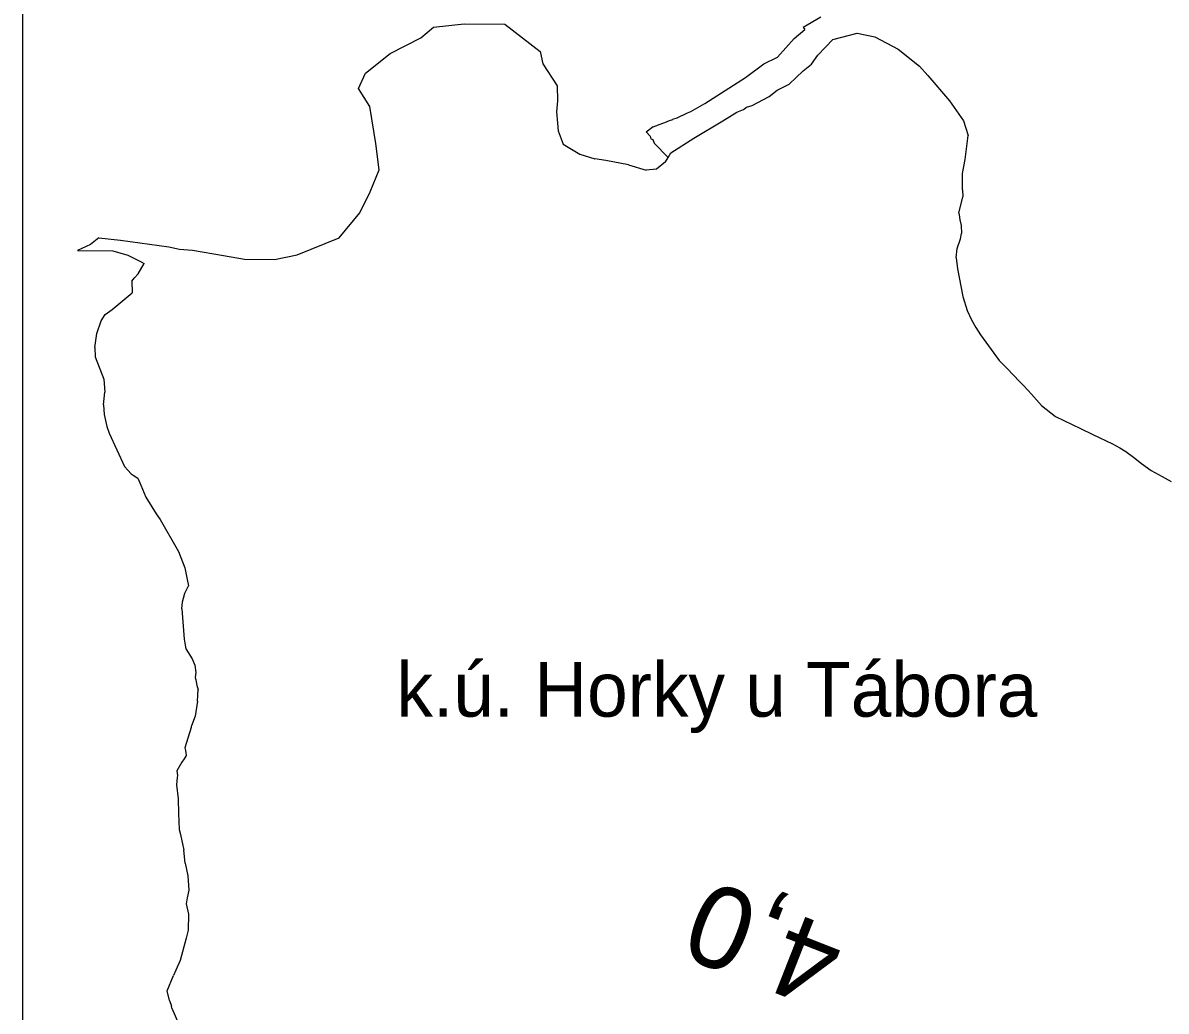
# Model space of a CAD drawing. Extents: x -738519 to -733269, y -1123734 to -1116309.
# Drawn here: x -738519 to -736425, y -1121302 to -1119491 of the extents above; entities that cross this region are included whole.
import ezdxf

# ---------------------------------------------------------------- set-up
doc = ezdxf.new("R2010")
doc.units = 0
for name, color, linetype in [('Implicitní', 7, 'Continuous'), ('Vrstva 13', 7, 'Continuous'), ('Vrstva 7', 7, 'Continuous')]:
    doc.layers.add(name, color=color, linetype=linetype)

msp = doc.modelspace()

# ---------------------------------------------------------------- linework, layer by layer
at = {"layer": 'Implicitní'}
msp.add_line((-738519, -1123733.5), (-738519, -1116308.5), dxfattribs=at)
at = {"layer": 'Vrstva 13'}
for p, q in [((-737089.5, -1119499.2), (-737057.3, -1119480.4)), ((-737789.9, -1119518.5), (-737766.9, -1119499.2)), ((-737766.9, -1119499.2), (-737710.7, -1119493)), ((-737710.7, -1119493), (-737636.1, -1119494)), ((-737636.1, -1119494), (-737571.5, -1119543.9)), ((-737105.9, -1119520.1), (-737086.5, -1119503.4)), ((-737089.5, -1119499.2), (-737086.5, -1119503.4)), ((-737846.4, -1119547.4), (-737789.9, -1119518.5)), ((-737136.4, -1119554), (-737105.9, -1119520.1)), ((-737062.6, -1119550.4), (-737035.1, -1119521.7)), ((-737062.6, -1119550.4), (-737035.1, -1119521.7)), ((-737035.1, -1119521.7), (-736991, -1119509.9)), ((-737035.1, -1119521.7), (-736991, -1119509.9)), ((-736991, -1119509.9), (-736958.4, -1119516.8)), ((-736991, -1119509.9), (-736958.4, -1119516.8)), ((-736958.4, -1119516.8), (-736915.6, -1119539.7)), ((-736958.4, -1119516.8), (-736915.6, -1119539.7)), ((-737891.6, -1119583.7), (-737846.4, -1119547.4)), ((-737571.5, -1119543.9), (-737566.6, -1119566.2)), ((-736915.6, -1119539.7), (-736876.5, -1119570.4)), ((-736915.6, -1119539.7), (-736876.5, -1119570.4)), ((-737566.6, -1119566.2), (-737540.1, -1119606.8)), ((-737195.3, -1119591.6), (-737161.8, -1119566.6)), ((-737161.8, -1119566.6), (-737136.4, -1119554)), ((-737089.4, -1119579.4), (-737074.6, -1119566.7)), ((-737089.4, -1119579.4), (-737074.6, -1119566.7)), ((-737074.6, -1119566.7), (-737062.6, -1119550.4)), ((-737074.6, -1119566.7), (-737062.6, -1119550.4)), ((-737904.4, -1119611.7), (-737891.6, -1119583.7)), ((-737115.2, -1119603.9), (-737089.4, -1119579.4)), ((-737115.2, -1119603.9), (-737089.4, -1119579.4)), ((-736876.5, -1119570.4), (-736861.5, -1119587.5)), ((-736876.5, -1119570.4), (-736861.5, -1119587.5)), ((-736861.5, -1119587.5), (-736821.7, -1119633.9)), ((-736861.5, -1119587.5), (-736821.7, -1119633.9)), ((-737540.1, -1119606.8), (-737539.8, -1119634.1)), ((-737269.5, -1119638.8), (-737195.3, -1119591.6)), ((-737137.1, -1119614.8), (-737115.2, -1119603.9)), ((-737137.1, -1119614.8), (-737115.2, -1119603.9)), ((-737883.2, -1119644.5), (-737904.4, -1119611.7)), ((-737182.8, -1119642.5), (-737151.6, -1119626.2)), ((-737182.8, -1119642.5), (-737151.6, -1119626.2)), ((-737151.6, -1119626.2), (-737137.1, -1119614.8)), ((-737151.6, -1119626.2), (-737137.1, -1119614.8)), ((-737872.5, -1119712.2), (-737883.2, -1119644.5)), ((-737539.8, -1119634.1), (-737541.7, -1119654.6)), ((-737295.5, -1119653.7), (-737269.5, -1119638.8)), ((-737210.9, -1119654.9), (-737199.1, -1119650.2)), ((-737210.9, -1119654.9), (-737199.1, -1119650.2)), ((-737199.1, -1119650.2), (-737193.7, -1119645.9)), ((-737199.1, -1119650.2), (-737193.7, -1119645.9)), ((-737193.7, -1119645.9), (-737182.8, -1119642.5)), ((-737193.7, -1119645.9), (-737182.8, -1119642.5)), ((-736821.7, -1119633.9), (-736795.8, -1119671)), ((-736821.7, -1119633.9), (-736795.8, -1119671)), ((-737541.7, -1119654.6), (-737539.8, -1119675.1)), ((-737346.6, -1119675), (-737342.9, -1119673.6)), ((-737342.9, -1119673.6), (-737334.2, -1119670.3)), ((-737334.2, -1119670.3), (-737328.4, -1119668.1)), ((-737328.5, -1119667.8), (-737320.4, -1119665.3)), ((-737328.5, -1119667.8), (-737328.4, -1119668.1)), ((-737320.4, -1119665.3), (-737301.5, -1119656.4)), ((-737301.5, -1119656.4), (-737295.5, -1119653.7)), ((-737290.1, -1119702.3), (-737236.5, -1119670.7)), ((-737290.1, -1119702.3), (-737236.5, -1119670.7)), ((-737236.5, -1119670.7), (-737210.9, -1119654.9)), ((-737236.5, -1119670.7), (-737210.9, -1119654.9)), ((-736795.8, -1119671), (-736787.1, -1119697.4)), ((-736795.8, -1119671), (-736787.1, -1119697.4)), ((-737539.8, -1119675.1), (-737538.7, -1119689.4)), ((-737538.7, -1119689.4), (-737529.1, -1119713.3)), ((-737377.3, -1119690.9), (-737364.1, -1119681)), ((-737377.3, -1119690.9), (-737370.1, -1119698.9)), ((-737364.1, -1119681.5), (-737346.6, -1119675)), ((-737364.1, -1119681), (-737364.1, -1119681.5)), ((-737866.4, -1119760.5), (-737872.5, -1119712.2)), ((-737529.1, -1119713.3), (-737498.5, -1119731.7)), ((-737370.1, -1119698.9), (-737368.4, -1119703.5)), ((-737368.4, -1119703.5), (-737365, -1119704.8)), ((-737365, -1119704.8), (-737362.6, -1119711.5)), ((-737362.6, -1119711.5), (-737337.2, -1119737.8)), ((-737332.3, -1119729.3), (-737290.1, -1119702.3)), ((-737332.3, -1119729.3), (-737290.1, -1119702.3)), ((-736793.1, -1119741.4), (-736787.1, -1119697.4)), ((-736793.1, -1119741.4), (-736787.1, -1119697.4)), ((-737498.5, -1119731.7), (-737471.2, -1119740.1)), ((-737337.2, -1119737.8), (-737332.3, -1119729.3)), ((-737337.2, -1119737.8), (-737332.3, -1119729.3)), ((-737451, -1119743.5), (-737471.2, -1119740.1)), ((-737409.7, -1119751.2), (-737451, -1119743.5)), ((-737409.7, -1119751.2), (-737377.1, -1119761)), ((-737341.9, -1119745.8), (-737358.2, -1119759.4)), ((-737341.9, -1119745.8), (-737337.2, -1119737.8)), ((-736797.5, -1119767.3), (-736793.1, -1119741.4)), ((-736797.5, -1119767.3), (-736793.1, -1119741.4)), ((-737882.5, -1119801), (-737866.4, -1119760.5)), ((-737358.2, -1119759.4), (-737377.1, -1119761)), ((-736798, -1119797), (-736797.5, -1119767.3)), ((-736798, -1119797), (-736797.5, -1119767.3)), ((-736798, -1119797), (-736797.3, -1119810.1)), ((-736798, -1119797), (-736797.3, -1119810.1)), ((-737901.8, -1119839.5), (-737882.5, -1119801)), ((-736804.4, -1119840.1), (-736797.3, -1119810.1)), ((-736804.4, -1119840.1), (-736797.3, -1119810.1)), ((-737939.5, -1119884.9), (-737901.8, -1119839.5)), ((-736804.4, -1119840.1), (-736804, -1119842.7)), ((-736804.4, -1119840.1), (-736804, -1119842.7)), ((-736804, -1119842.7), (-736802.6, -1119851.9)), ((-736804, -1119842.7), (-736802.6, -1119851.9)), ((-736802.6, -1119851.9), (-736800.2, -1119862.8)), ((-736802.6, -1119851.9), (-736800.2, -1119862.8)), ((-736801.5, -1119887), (-736799.4, -1119876.9)), ((-736801.5, -1119887), (-736799.4, -1119876.9)), ((-736800.2, -1119862.8), (-736799.4, -1119876.9)), ((-736800.2, -1119862.8), (-736799.4, -1119876.9)), ((-738395, -1119897.1), (-738418.9, -1119908.4)), ((-738379.9, -1119885), (-738395, -1119897.1)), ((-738379.9, -1119885), (-738340.4, -1119889.2)), ((-738340.4, -1119889.2), (-738251.5, -1119901.8)), ((-738251.5, -1119901.8), (-738232.3, -1119905.7)), ((-738016.3, -1119916.2), (-737939.5, -1119884.9)), ((-736809.4, -1119921.7), (-736807.6, -1119904.4)), ((-736809.4, -1119921.7), (-736807.6, -1119904.4)), ((-736807.6, -1119904.4), (-736801.5, -1119887)), ((-736807.6, -1119904.4), (-736801.5, -1119887)), ((-738418.9, -1119908.4), (-738354.1, -1119908.9)), ((-738354.1, -1119908.9), (-738326.6, -1119917.1)), ((-738326.6, -1119917.1), (-738299.8, -1119930.6)), ((-738232.3, -1119905.7), (-738208.2, -1119907.5)), ((-738208.2, -1119907.5), (-738151.5, -1119917.5)), ((-738151.5, -1119917.5), (-738112.9, -1119924.2)), ((-738112.9, -1119924.2), (-738058, -1119925.1)), ((-738058, -1119925.1), (-738016.3, -1119916.2)), ((-736809.4, -1119921.7), (-736807, -1119942.2)), ((-736809.4, -1119921.7), (-736807, -1119942.2)), ((-738308, -1119950.8), (-738296.6, -1119932.4)), ((-738299.8, -1119930.6), (-738298.4, -1119931.3)), ((-738298.4, -1119931.3), (-738296.6, -1119932.4)), ((-736807, -1119942.2), (-736797.3, -1119992.8)), ((-736807, -1119942.2), (-736797.3, -1119992.8)), ((-738319.2, -1119964.2), (-738314.7, -1119958.5)), ((-738319.2, -1119964.2), (-738318.9, -1119985.9)), ((-738314.7, -1119958.5), (-738308, -1119950.8)), ((-738355.6, -1120016.2), (-738318.9, -1119985.9)), ((-736797.3, -1119992.8), (-736789.2, -1120018)), ((-736797.3, -1119992.8), (-736789.2, -1120018)), ((-738375.3, -1120037.4), (-738368.5, -1120025.8)), ((-738368.5, -1120025.8), (-738355.6, -1120016.2)), ((-736789.2, -1120018), (-736781.5, -1120035.6)), ((-736789.2, -1120018), (-736781.5, -1120035.6)), ((-738383.6, -1120060.2), (-738375.3, -1120037.4)), ((-736781.5, -1120035.6), (-736773.3, -1120049.4)), ((-736781.5, -1120035.6), (-736773.3, -1120049.4)), ((-736773.3, -1120049.4), (-736764.6, -1120062.9)), ((-736773.3, -1120049.4), (-736764.6, -1120062.9)), ((-738387.3, -1120085.8), (-738383.6, -1120060.2)), ((-736764.6, -1120062.9), (-736730.3, -1120109.6)), ((-736764.6, -1120062.9), (-736730.3, -1120109.6)), ((-738387.3, -1120085.8), (-738386.4, -1120103.3)), ((-738386.4, -1120103.3), (-738370.9, -1120144.2)), ((-736730.3, -1120109.6), (-736716.5, -1120124.1)), ((-736730.3, -1120109.6), (-736716.5, -1120124.1)), ((-736716.5, -1120124.1), (-736692.6, -1120149.1)), ((-736716.5, -1120124.1), (-736692.6, -1120149.1)), ((-738370.9, -1120144.2), (-738369, -1120167.8)), ((-736692.6, -1120149.1), (-736686.1, -1120155.9)), ((-736692.6, -1120149.1), (-736686.1, -1120155.9)), ((-738371.2, -1120190.9), (-738369, -1120167.8)), ((-736686.1, -1120155.9), (-736678.1, -1120164.3)), ((-736686.1, -1120155.9), (-736678.1, -1120164.3)), ((-736671.5, -1120171.6), (-736678.1, -1120164.3)), ((-736671.5, -1120171.6), (-736678.1, -1120164.3)), ((-736653.1, -1120192.1), (-736671.5, -1120171.6)), ((-736653.1, -1120192.1), (-736671.5, -1120171.6)), ((-738371.2, -1120190.9), (-738369.9, -1120208.9)), ((-736653.1, -1120192.1), (-736627.5, -1120212.6)), ((-736653.1, -1120192.1), (-736627.5, -1120212.6)), ((-738369.9, -1120208.9), (-738365.1, -1120230.7)), ((-736627.5, -1120212.6), (-736581.6, -1120234.7)), ((-736627.5, -1120212.6), (-736581.6, -1120234.7)), ((-738365.1, -1120230.7), (-738360.8, -1120242.7)), ((-736581.6, -1120234.7), (-736559, -1120245.3)), ((-736581.6, -1120234.7), (-736559, -1120245.3)), ((-738360.8, -1120242.7), (-738332.5, -1120303.8)), ((-736559, -1120245.3), (-736523.2, -1120262.2)), ((-736559, -1120245.3), (-736523.2, -1120262.2)), ((-736523.2, -1120262.2), (-736509.3, -1120269.9)), ((-736523.2, -1120262.2), (-736509.3, -1120269.9)), ((-736509.3, -1120269.9), (-736498.6, -1120276.6)), ((-736509.3, -1120269.9), (-736498.6, -1120276.6)), ((-736498.6, -1120276.6), (-736484.7, -1120286.8)), ((-736498.6, -1120276.6), (-736484.7, -1120286.8)), ((-736484.7, -1120286.8), (-736470, -1120298.8)), ((-736484.7, -1120286.8), (-736470, -1120298.8)), ((-736470, -1120298.8), (-736452.4, -1120311.2)), ((-736470, -1120298.8), (-736452.4, -1120311.2)), ((-738332.5, -1120303.8), (-738320.4, -1120317.4)), ((-738320.4, -1120317.4), (-738316.8, -1120319.7)), ((-738316.8, -1120319.7), (-738308.5, -1120325.1)), ((-736452.4, -1120311.2), (-736431.9, -1120322.4)), ((-736452.4, -1120311.2), (-736431.9, -1120322.4)), ((-736431.9, -1120322.4), (-736415.6, -1120331.4)), ((-736431.9, -1120322.4), (-736415.6, -1120331.4)), ((-738308.5, -1120325.1), (-738303, -1120338)), ((-738303, -1120338), (-738293.5, -1120360.2)), ((-738293.5, -1120360.2), (-738274.7, -1120390.5)), ((-738274.7, -1120390.5), (-738267.5, -1120401.4)), ((-738267.5, -1120401.4), (-738233.6, -1120460)), ((-738233.6, -1120460), (-738222.2, -1120489.6)), ((-738222.2, -1120489.6), (-738217.8, -1120511.1)), ((-738217.8, -1120511.1), (-738215.6, -1120522.4)), ((-738222.2, -1120536.3), (-738215.6, -1120522.4)), ((-738227.6, -1120564.8), (-738226.3, -1120552.2)), ((-738226.3, -1120552.2), (-738224.6, -1120545.3)), ((-738224.6, -1120545.3), (-738222.2, -1120536.3)), ((-738227.6, -1120564.8), (-738223.5, -1120620.6)), ((-738223.5, -1120620.6), (-738221.5, -1120631.6)), ((-738221.5, -1120631.6), (-738220.2, -1120637.8)), ((-738220.2, -1120637.8), (-738208.9, -1120656.2)), ((-738208.9, -1120656.2), (-738204.2, -1120667.7)), ((-738204.2, -1120667.7), (-738202.1, -1120681.5)), ((-738202.1, -1120681.5), (-738203.1, -1120690.8)), ((-738203.1, -1120690.8), (-738202.4, -1120694.6)), ((-738202.4, -1120694.6), (-738200.4, -1120705)), ((-738200.4, -1120705), (-738197.8, -1120712.7)), ((-738198.8, -1120733.9), (-738197.8, -1120712.7)), ((-738198.8, -1120733.9), (-738203.3, -1120761.2)), ((-738203.3, -1120761.2), (-738209.9, -1120779)), ((-738210.8, -1120782), (-738222.2, -1120819.1)), ((-738210.4, -1120780.6), (-738210.8, -1120782)), ((-738209.9, -1120779), (-738210.4, -1120780.6)), ((-738222.2, -1120819.1), (-738221.3, -1120824.4)), ((-738221.3, -1120824.4), (-738220.5, -1120828.6)), ((-738227.5, -1120845.9), (-738237.1, -1120861.3)), ((-738223.7, -1120839.8), (-738227.5, -1120845.9)), ((-738219.7, -1120833.4), (-738223.7, -1120839.8)), ((-738220.5, -1120828.6), (-738219.7, -1120833.4)), ((-738237.1, -1120861.3), (-738235.7, -1120870)), ((-738236.2, -1120873.8), (-738237.7, -1120887.1)), ((-738237.7, -1120887.1), (-738234.3, -1120913.1)), ((-738235.7, -1120870), (-738236.2, -1120873.8)), ((-738234.3, -1120913.1), (-738234, -1120939.6)), ((-738234, -1120939.6), (-738232.4, -1120968.7)), ((-738232.4, -1120968.7), (-738230.2, -1120978.4)), ((-738230.2, -1120978.4), (-738223.8, -1121006.7)), ((-738221.4, -1121030.6), (-738223.8, -1121006.7)), ((-738221.4, -1121030.6), (-738216.9, -1121054.1)), ((-738216.9, -1121054.1), (-738214.9, -1121079.9)), ((-738217.7, -1121094.1), (-738219.8, -1121104.9)), ((-738214.9, -1121079.9), (-738217.7, -1121094.1)), ((-738219.8, -1121104.9), (-738215.6, -1121124.4)), ((-738215.6, -1121124.4), (-738216.3, -1121153.6)), ((-738216.3, -1121153.6), (-738220.1, -1121168.2)), ((-738220.1, -1121168.2), (-738230.6, -1121208.7)), ((-738230.6, -1121208.7), (-738238.5, -1121226.9)), ((-738254.5, -1121264.3), (-738242.8, -1121236.7)), ((-738238.5, -1121226.9), (-738242.8, -1121236.7)), ((-738250.4, -1121282), (-738254.5, -1121264.3)), ((-738250.4, -1121282), (-738246.8, -1121292.8)), ((-738245.8, -1121296), (-738246.8, -1121292.8)), ((-738245.8, -1121296), (-738233.9, -1121324.5))]:
    msp.add_line(p, q, dxfattribs=at)

# ---------------------------------------------------------------- texts
msp.add_text('k.ú. Horky u Tábora', height=100, dxfattribs=at).set_placement((-737834.7, -1120762.3))
at = {"layer": 'Vrstva 7'}
msp.add_text('4,0', height=150, rotation=158.5969, dxfattribs=at).set_placement((-737005.4, -1121160.6))

doc.saveas('drawing.dxf')
